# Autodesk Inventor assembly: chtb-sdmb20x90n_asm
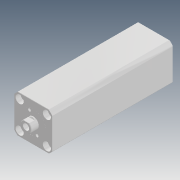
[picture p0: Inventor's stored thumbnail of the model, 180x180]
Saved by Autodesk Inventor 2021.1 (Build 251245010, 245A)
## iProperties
Company: Microsoft
Created: 2018-05
Part Number: chtb-sdmb20x90n_asm
Description: STEP AP214
Document SubType Name: Assembly
Designer: user
Title: chtb-sdmb20x90n_asm.STEP
Author: Windows
Revision Number: ÈÎºÎ
Sending System: SolidWorks 2015
Preprocessor: SwSTEP 2.0
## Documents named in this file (4)
- D:\Vault_2016\Projekty\Clamptek\Hydraulic\CHTB\CHTB-20\Inventor\CHTB-SDMB20x90N\chtb-sdmb20x90n_asm.iam
- D:\Vault_2016\Projekty\Clamptek\Hydraulic\CHTB\CHTB-20\Inventor\CHTB-SDMB20x90N\CHTB-SDMB20X90NBT.ipt
- D:\Vault_2016\Projekty\Clamptek\Hydraulic\CHTB\CHTB-20\Inventor\CHTB-SDMB20x90N\CHTB-SDMB20X90NHSG.ipt
- D:\Vault_2016\Projekty\Clamptek\Hydraulic\CHTB\CHTB-20\Inventor\CHTB-SDMB20x90N\QG_3.ipt
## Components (3 placed, 3 different names)
1. CHTB-SDMB20X90NBT_1
2. CHTB-SDMB20X90NHSG_2
3. QG_3_3
